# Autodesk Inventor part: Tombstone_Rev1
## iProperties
Created: 2008-11
Part Number: Tombstone_Rev1
Document SubType Name: Modeling
Designer: claivier
Author: claivier
Norme de conversion: STEP AP214IS
Nom du fichier: Tombstone_Rev1.STEP
Préprocesseur: SolidWorks 2008
Postprocesseur: Build: 344a, Release: 11 SP2 - Date: Fri 08/18/2006
Unités envoyées: INCHES
Incertitude: 1e-05
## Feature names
1. Base1
